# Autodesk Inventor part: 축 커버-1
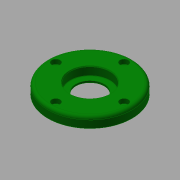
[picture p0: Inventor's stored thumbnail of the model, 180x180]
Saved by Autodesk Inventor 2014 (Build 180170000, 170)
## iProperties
Created: 2015-10
Part Number: 축 커버-1
Document SubType Name: Modeling
Designer: mdu
Density: 7.86 g/cm^3
Material: 강철, 연강
Appearance: 진녹색
Mass: 321.443 g
Surface Area: 134.096 cm^2
Volume: 40.896 cm^3
Author: mdu
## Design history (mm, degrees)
sketch "스케치1"
  geometry: C1 r 40 at (0, 0) reference; C2 r 26 at (0, 0) reference; 1 further point
  node "참조1"
  node "참조2"
extrude "돌출1" new body sketch "스케치1" distance "d0" = 10; taper "d1" = 0 deg
extrude "돌출2" join sketch "스케치1" distance "d2" = 3; taper "d3" = 0 deg
hole "구멍1" diameter "d6" = 27; stored, may be unused: countersink angle "d10" = 90 deg, drill point angle "d12" = 118 deg; dims "d7" = 6, "d8" = 38, "d9" = 8.3, "d11" = 8, "d31" = 10, "d32" = 10
sketch "스케치2"
  geometry: C1 r 20 at (0, 0); 1 further point
  constraints: 1 centre point, 1 coincident
  dimensions: "d13" = 40 diameter of C1
extrude "돌출3" cut sketch "스케치2" distance "d14" = 3; taper "d15" = 0 deg
sketch "스케치3"
  geometry: C1 r 1.621 at (0, 32.5) reference; 1 further point
hole "구멍2" sketch "스케치3" at (0, 32.5) diameter "d16" = 4.5; stored, may be unused: countersink angle "d20" = 90 deg, drill point angle "d22" = 118 deg; dims "d17" = 6, "d18" = 8, "d19" = 4.4, "d21" = 8
fillet "모깎기1" dims "d26" = 3, "d27" = 0.3
chamfer "모따기1" distance "d28" = 1; stored, may be unused: second distance "d29" = 2, angle "d30" = 45 deg
chamfer "모따기2" distance "d33" = 0.8; stored, may be unused: second distance "d34" = 2, angle "d35" = 30 deg
node "솔리드1"
pattern_circular "원형 패턴1" dims angle "d24" = 360 deg
node "참조3"
